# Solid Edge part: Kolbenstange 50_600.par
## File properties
Username: ahadarics
Dokumentum tartalom típus: 0
Author: ahadarics
Last saved by: ahadarics
Revision: 93
Sűrűség: 0,000 kg/m^3
Pontosság: 0,990
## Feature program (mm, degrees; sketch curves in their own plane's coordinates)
base feature "unnamed BaseFeature 1"
thread "unnamed Thread 1"
chamfer "Letörés_1"  SetBackValue2 = 20 deg
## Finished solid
Body 1: solid body, 21 faces, 32 edges, 14 vertices.
  Faces by surface: plane 8, cylinder 5, cone 4, torus 4
  Edges by curve: circle 17, line 9, curve on surface 4, ellipse 2
Bounding box of the edges (mm; curved faces can reach further): 50.000 x 50.000 x 744.000, from (-25, -25, -86.5) to (25, 25, 657.5).
Cylindrical faces by radius (mm): R6.75 x1, R8 x1, R9.75 x1, R10 x1, R25 x1
Conical faces (half-angle, radius in mm at the cone's reference point): 20 deg R8 x1, 30 deg R9.875 x1, 45 deg R24.25 x1, 60 deg R7.375 x1
Toroidal faces (ring radius, tube radius in mm): R7.15 r0.4 x2, R8.55 r1.2 x2
Planar faces by outward normal: +x 1, +z 3, -x 1, -z 1, oblique 2
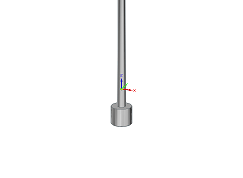
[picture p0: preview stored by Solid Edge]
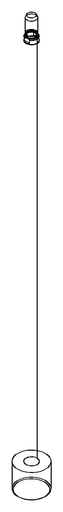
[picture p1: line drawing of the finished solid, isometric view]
